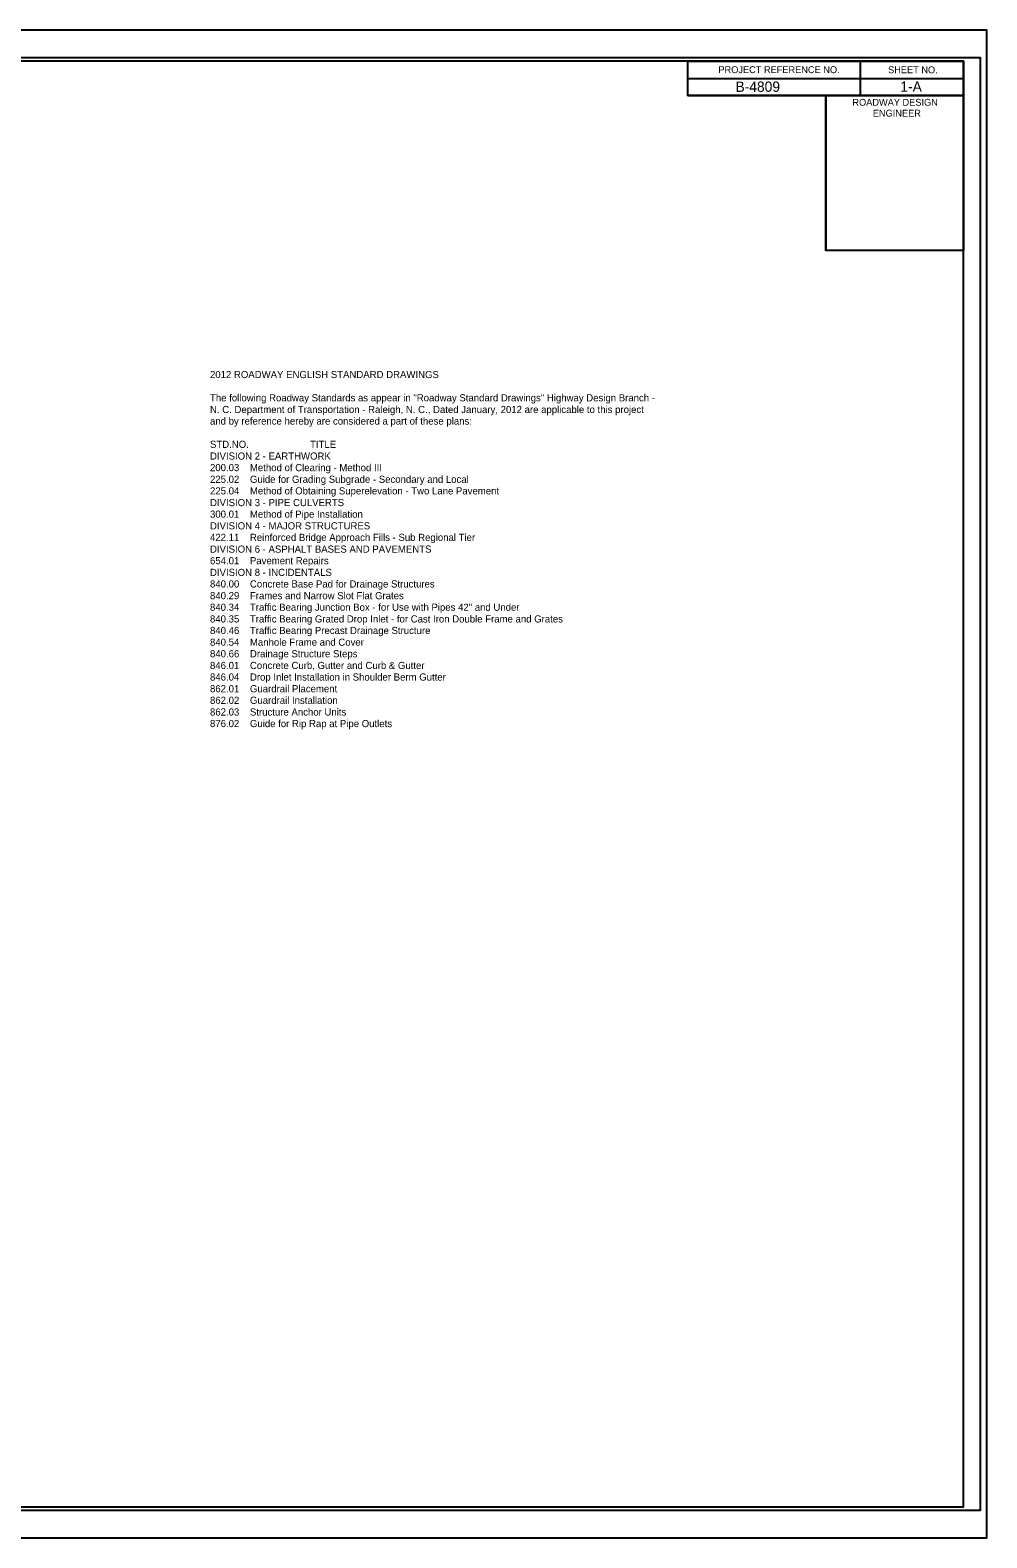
# Model space of a CAD drawing. Extents: x 9834 to 11517, y 9978 to 11072.
# Drawn here: x 10822 to 11517, y 9978 to 11072 of the extents above; entities that cross this region are included whole.
import ezdxf

# ---------------------------------------------------------------- set-up
doc = ezdxf.new("R2010")
doc.units = 0
for name, color, linetype in [('Default', 7, 'Continuous'), ('Sheet Cutting Line CELL', 7, 'Continuous'), ('Sheet Data Field CELL', 7, 'Continuous'), ('Sheet Plan CELL', 7, 'Continuous'), ('Sheet Plot Border Inside CELL', 7, 'Continuous'), ('Sheet Plot Border Outside CELL', 7, 'Continuous')]:
    doc.layers.add(name, color=color, linetype=linetype)

msp = doc.modelspace()

# ---------------------------------------------------------------- linework, layer by layer
at = {"layer": 'Sheet Cutting Line CELL'}
for p, q in [((11517, 11072.5), (9833.5, 11072.5)), ((9833.5, 9977.5), (11517, 9977.5))]:
    msp.add_line(p, q, dxfattribs=at)
at = {"layer": 'Sheet Plan CELL'}
for p, q in [((11425, 11050), (11425, 11025)), ((11300, 11037.5), (11500, 11037.5)), ((11300, 11025), (11500, 11025)), ((11300, 11025), (11500, 11025)), ((11400, 11025), (11400, 10912.5))]:
    msp.add_line(p, q, dxfattribs=at)
for points in [[(11500, 11050), (10000, 11050), (10000, 10000), (11500, 10000)], [(11300, 11050), (11500, 11050), (11500, 11025), (11300, 11025)], [(11400, 11025), (11500, 11025), (11500, 10912.5), (11400, 10912.5)]]:
    msp.add_lwpolyline(points, close=True, dxfattribs=at)
at = {"layer": 'Sheet Plot Border Inside CELL'}
msp.add_lwpolyline([(9846.5, 9997.5), (11512.5, 9997.5), (11512.5, 11052.5), (9846.5, 11052.5)], close=True, dxfattribs=at)
at = {"layer": 'Sheet Plot Border Outside CELL'}
msp.add_lwpolyline([(9833.5, 9977.5), (11517, 9977.5), (11517, 11072.5), (9833.5, 11072.5)], close=True, dxfattribs=at)

# ---------------------------------------------------------------- texts
at = {"layer": 'Default'}
for s, p in [('2012 ROADWAY ENGLISH STANDARD DRAWINGS', (10953, 10819.8)), ('The following Roadway Standards as appear in "Roadway Standard Drawings" Highway Design Branch -', (10953, 10802.9)), ('N. C. Department of Transportation - Raleigh, N. C., Dated January, 2012 are applicable to this project', (10953, 10794.4)), ('and by reference hereby are considered a part of these plans:', (10953, 10786)), ('STD.NO.                       TITLE', (10953, 10769.1)), ('DIVISION 2 - EARTHWORK', (10953, 10760.6)), ('200.03    Method of Clearing - Method III', (10953, 10752.2)), ('225.02    Guide for Grading Subgrade - Secondary and Local', (10953, 10743.7)), ('225.04    Method of Obtaining Superelevation - Two Lane Pavement', (10953, 10735.3)), ('DIVISION 3 - PIPE CULVERTS', (10953, 10726.8)), ('300.01    Method of Pipe Installation ', (10953, 10718.4)), ('DIVISION 4 - MAJOR STRUCTURES', (10953, 10709.9)), ('422.11    Reinforced Bridge Approach Fills - Sub Regional Tier', (10953, 10701.5)), ('DIVISION 6 - ASPHALT BASES AND PAVEMENTS', (10953, 10693)), ('654.01    Pavement Repairs', (10953, 10684.6)), ('DIVISION 8 - INCIDENTALS', (10953, 10676.1)), ('840.00    Concrete Base Pad for Drainage Structures', (10953, 10667.7)), ('840.29    Frames and Narrow Slot Flat Grates', (10953, 10659.2)), ('840.34    Traffic Bearing Junction Box - for Use with Pipes 42" and Under', (10953, 10650.8)), ('840.35    Traffic Bearing Grated Drop Inlet - for Cast Iron Double Frame and Grates', (10953, 10642.3)), ('840.46    Traffic Bearing Precast Drainage Structure', (10953, 10633.9)), ('840.54    Manhole Frame and Cover', (10953, 10625.4)), ('840.66    Drainage Structure Steps', (10953, 10617)), ('846.01    Concrete Curb, Gutter and Curb & Gutter', (10953, 10608.5)), ('846.04    Drop Inlet Installation in Shoulder Berm Gutter', (10953, 10600.1)), ('862.01    Guardrail Placement', (10953, 10591.6)), ('862.02    Guardrail Installation', (10953, 10583.2)), ('862.03    Structure Anchor Units', (10953, 10574.7)), ('876.02    Guide for Rip Rap at Pipe Outlets', (10953, 10566.3))]:
    msp.add_text(s, height=5.2, dxfattribs=at).set_placement(p)
at = {"layer": 'Sheet Data Field CELL'}
for s, p in [('B-4809   ', (11334.5, 11027.7)), ('1-A', (11454.2, 11027.8))]:
    msp.add_text(s, height=7.5, dxfattribs=at).set_placement(p)
at = {"layer": 'Sheet Plan CELL'}
for s, p in [('PROJECT REFERENCE NO.', (11322.1, 11041.3)), ('SHEET NO.', (11445.3, 11041.2)), ('ROADWAY DESIGN', (11419.4, 11017.6)), ('ENGINEER', (11434.2, 11009.7))]:
    msp.add_text(s, height=5, dxfattribs=at).set_placement(p)

doc.saveas('drawing.dxf')
